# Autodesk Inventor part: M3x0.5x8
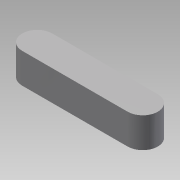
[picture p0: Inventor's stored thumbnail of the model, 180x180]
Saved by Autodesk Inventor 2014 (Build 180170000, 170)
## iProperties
Company: 한국ATC센터
Created: 2009-02
Part Number: M3x0.5x8
Document SubType Name: Modeling
Designer: KYOUNG IL JANG
Density: 7.86 g/cm^3
Mass: 2.15573 g
Surface Area: 2.99398 cm^2
Volume: 0.274265 cm^3
Vendor: CBT Solutions
Material: 강철, 연강
Appearance: 강철
Author: KYOUNG IL JANG
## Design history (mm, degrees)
sketch "스케치1"
  geometry: L1 (0, 2)-(14, 2); L2 (0, -2)-(14, -2); A1 r 2 centre (0, 0) between (0, 2) and (0, -2); A2 r 2 centre (14, 0) between (14, -2) and (14, 2); 1 further point
  constraints: 4 end point, 4 point on circle, 3 tangent, 2 centre point, 1 coincident, 1 equal radius, 1 horizontal alignment, 1 parallel
  dimensions: "d0" = 4 distance between parallel lines of L2 L1; "d1" = 18 dimension on A2 A1
extrude "돌출1" new body sketch "스케치1" distance "d2" = 4; taper "d3" = 0 deg
node "솔리드1"
